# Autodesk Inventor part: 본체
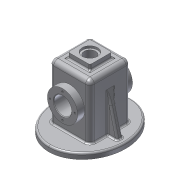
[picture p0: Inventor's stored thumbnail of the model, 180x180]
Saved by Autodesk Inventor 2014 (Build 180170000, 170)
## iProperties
Created: 2017-07
Part Number: 본체
Material: Aluminum 6061
Document SubType Name: Modeling
Designer: user
Density: 2.71 g/cm^3
Appearance: Aluminum - Flat
Author: user
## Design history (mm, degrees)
sketch "Sketch1"
  geometry: L1 (0, 0)-(74, 0); L2 (74, 0)-(74, 100); L3 (74, 100)-(0, 100); L4 (0, 100)-(0, 0)
  constraints: 8 end point, 2 parallel, 1 horizontal, 1 perpendicular
  dimensions: "d0" = 74 distance of L1.start L1.end; "d1" = 100 distance of L1.end L2.end
extrude "Extrusion1" new body sketch "Sketch1" distance "d2" = 74; taper "d3" = 0 deg
workplane "Work Plane1"
sketch "Sketch4"
  geometry: L1 (74, 0)-(74, 100) reference; L2 (74, 100)-(0, 100) reference; C1 r 27.5 at (37, 50); 3 further points
  constraints: 2 midpoint, 1 centre point, 1 horizontal alignment, 1 vertical alignment
  dimensions: "d4" = 55 diameter of C1
extrude "Extrusion2" join sketch "Sketch4" stored distance "d5" = 100; taper "d6" = 0 deg
sketch "Sketch7"
  geometry: C1 r 27.5 at (0, 0) reference; C2 r 16 at (0, 0); 1 further point
  constraints: 1 centre point, 1 coincident
  dimensions: "d18" = 32 diameter of C2
extrude "Extrusion4" cut sketch "Sketch7" stored distance "d19" = 10; taper "d20" = 0 deg
sketch "Sketch8" dims "d21" = 45
  geometry: L1 (0, 0)-(0, 22.5); C1 r 27.5 at (0, 0) reference; 2 further points
  constraints: 2 coincident, 2 end point, 1 vertical, 1 vertical alignment, 2 other
hole "Hole1" sketch "Sketch8" at (0, 22.5) diameter "d22" = 3.242; stored, may be unused: countersink angle "d26" = 90 deg, drill point angle "d28" = 118 deg; dims "d23" = 8, "d24" = 4, "d25" = 2, "d27" = 10
pattern_circular "Circular Pattern1" dims angle "d30" = 360 deg
mirror "Mirror1"
sketch "Sketch10"
  geometry: L1 (102, 111.753)-(-28, 111.753); L2 (-28, 111.753)-(-28, -38); L3 (-28, -38)-(102, -38); L4 (102, -38)-(102, 111.753); L5 (74, 0)-(0, 74); L6 (74, 74)-(0, 0); 2 further points; 1 other entity
  constraints: 12 end point, 3 horizontal, 2 parallel, 2 perpendicular, 2 vertical, 1 coincident, 1 midpoint, 2 other
  dimensions: "d32" = 75 distance from line of point (37, 37) L3; "d33" = 65 distance from line of point (37, 37) L4
extrude "Extrusion5" join sketch "Sketch10" distance "d34" = 10; taper "d35" = 0 deg
sketch "Sketch12"
  geometry: L1 (74, -74)-(0, -74) reference; L2 (74, 0)-(74, -74) reference; L3 (57, -57)-(17, -57); L4 (17, -57)-(17, -17); L5 (17, -17)-(57, -17); L6 (57, -17)-(57, -57); L7 (57, -57)-(17, -17); L8 (17, -57)-(57, -17); 5 further points
  constraints: 12 end point, 6 midpoint, 2 parallel, 2 perpendicular, 1 horizontal, 1 horizontal alignment, 1 vertical alignment
  dimensions: "d36" = 40 distance of L3.end L4.end
extrude "Extrusion6" join sketch "Sketch12" distance "d37" = 10; taper "d38" = 0 deg
sketch "Sketch13"
  geometry: L1 (57, -57)-(57, -17) reference; L2 (57, -17)-(17, -17) reference; C1 r 14 at (37, -37); 3 further points
  constraints: 2 midpoint, 1 centre point, 1 horizontal alignment, 1 vertical alignment
  dimensions: "d39" = 28 diameter of C1
extrude "Extrusion7" cut sketch "Sketch13" distance "d40" = 4; taper "d41" = 0 deg
sketch "Sketch14"
  geometry: C1 r 14 at (0, 0) reference; C2 r 10.5 at (0, 0); 1 further point
  constraints: 1 centre point, 1 coincident
  dimensions: "d42" = 21 diameter of C2
extrude "Extrusion8" cut sketch "Sketch14" stored distance "d43" = 4; taper "d44" = 0 deg
sketch "Sketch16"
  geometry: L1 (92, 0)-(74, 72.194); L2 (74, 0)-(74, 100) reference; L3 (102, 0)-(-28, 0) reference; 2 further points
  constraints: 2 end point, 2 point on line, 1 coincident
  dimensions: "d45" = 104 deg angle of L3 L1; "d58" = 10 distance of L3.start point (92, 0)
extrude "Extrusion9" join sketch "Sketch16" stored distance "d46" = 10; taper "d47" = 0 deg
workplane "Work Plane2"
mirror "Mirror2"
fillet "Fillet1" dims "d48" = 3
fillet "Fillet2" dims "d49" = 8
fillet "Fillet3" dims "d50" = 8
fillet "Fillet4" dims "d51" = 3
fillet "Fillet5" dims "d52" = 3
fillet "Fillet6" dims "d53" = 3
fillet "Fillet7" dims "d54" = 3
chamfer "Chamfer1" distance "d55" = 1; stored, may be unused: second distance "d56" = 2, angle "d57" = 45 deg
sketch "Sketch17"
  geometry: 1 further point
sketch "Sketch18"
  geometry: L1 (5, 5)-(69, 5); L2 (69, 5)-(69, 69); L3 (69, 69)-(5, 69); L4 (5, 69)-(5, 5); L5 (5, 5)-(69, 69); L6 (69, 5)-(5, 69); C1 r 10.5 at (37, 37) reference; 2 further points; 1 other entity
  constraints: 12 end point, 2 midpoint, 2 parallel, 2 perpendicular, 1 horizontal, 1 other
  dimensions: "d59" = 64 distance of L2.end L3.end
extrude "Extrusion10" cut sketch "Sketch18" distance "d60" = 22.5; taper "d61" = 0 deg
sketch "Sketch19"
  geometry: L1 (0, 3)-(0, 92) reference; L2 (-54, 110)-(-20, 110) reference; 2 further points
  constraints: 1 other
  dimensions: "d62" = 37 distance from line of point (-37, 80) L1; "d63" = 30 distance from line of L2 point (-37, 80)
emboss "Emboss1" sketch "Sketch19" dims "d0" = 74, "d1" = 100, "d19" = 10, "d20" = 0, "d64" = 0.5, "d65" = 0
body "Solid1"
